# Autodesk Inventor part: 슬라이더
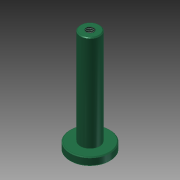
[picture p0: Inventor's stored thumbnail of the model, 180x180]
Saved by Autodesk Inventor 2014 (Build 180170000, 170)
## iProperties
Created: 2016-02
Part Number: 슬라이더
Material: 스테인레스 스틸
Document SubType Name: Modeling
Designer: mduedu
Density: 8.08 g/cm^3
Mass: 72.5507 g
Surface Area: 37.669 cm^2
Volume: 8.97904 cm^3
Appearance: 매끄러움 - 짙은 바다 녹색
Author: mduedu
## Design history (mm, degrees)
sketch "스케치1"
  geometry: C1 r 12.5 at (0, 0); 1 further point
  constraints: 1 centre point, 1 coincident
  dimensions: "d0" = 25 diameter of C1
extrude "돌출1" new body sketch "스케치1" distance "d1" = 5; taper "d2" = 0 deg
sketch "스케치2"
  geometry: C1 r 6 at (0, 0); 1 further point
  constraints: 1 centre point, 1 coincident
  dimensions: "d3" = 12 diameter of C1
extrude "돌출2" join sketch "스케치2" distance "d4" = 60; taper "d5" = 0 deg
chamfer "모따기1" distance "d6" = 0.5; stored, may be unused: second distance "d7" = 2, angle "d8" = 45 deg
hole "구멍1" diameter "d11" = 4.917; stored, may be unused: countersink angle "d15" = 90 deg, drill point angle "d17" = 118 deg; dims "d9" = 10, "d10" = 10, "d12" = 10, "d13" = 4, "d14" = 2, "d16" = 12
chamfer "모따기2" distance "d18" = 0.5; stored, may be unused: second distance "d19" = 2, angle "d20" = 45 deg
sketch "스케치3"
  geometry: L1 (-12.5, 4.5)-(-12, 5) reference; L2 (-12, 5)-(-6, 5) reference; L3 (-6, 5)-(-6, 64.5) reference; L4 (-6, 64.5)-(-5.5, 65) reference; L5 (-5.5, 65)-(-2.458, 65) reference; L6 (-2.458, 65)-(-2.458, 53) reference; L7 (-2.458, 53)-(0, 51.523) reference; L8 (0, 51.523)-(2.458, 53) reference; L9 (2.458, 53)-(2.458, 65) reference; L10 (2.458, 65)-(5.5, 65) reference; L11 (5.5, 65)-(6, 64.5) reference; L12 (6, 64.5)-(6, 5) reference; L13 (6, 5)-(12, 5) reference; L14 (12, 5)-(12.5, 4.5) reference; L15 (12.5, 4.5)-(12.5, 0.5) reference; L16 (12.5, 0.5)-(12, 0) reference; L17 (12, 0)-(-12, 0) reference; L18 (-12, 0)-(-12.5, 0.5) reference; L19 (-12.5, 0.5)-(-12.5, 4.5) reference; 1 further point
  node "절단 모서리 투영1"
node "솔리드1"
